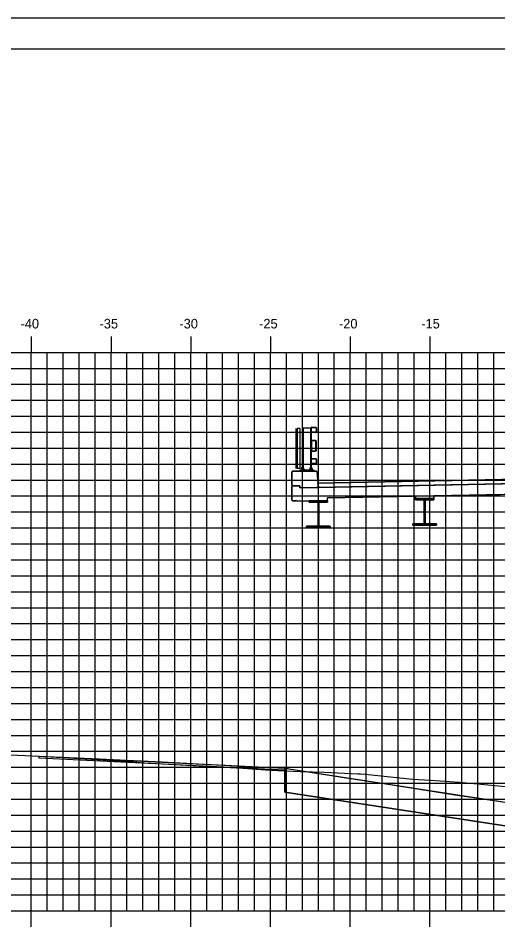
# Model space of a CAD drawing. Extents: x -22 to 1480, y -1511 to 8.
# Drawn here: x 463.6 to 493.7, y -131.7 to -74.5 of the extents above; entities that cross this region are included whole.
import ezdxf

# ---------------------------------------------------------------- set-up
doc = ezdxf.new("R2010")
doc.units = 0
for name, color, linetype in [('BORDER', 7, 'Continuous'), ('D_Bridge_Deck', 7, 'Continuous'), ('D_Bridge_Railing', 7, 'Continuous'), ('D_Bridge_Superstructure', 7, 'Continuous'), ('D_Bridge_Superstructure_Slab', 7, 'Continuous'), ('D_Roadway_Centerline', 7, 'Continuous'), ('D_Roadway_Edge_Shoulder', 7, 'Continuous'), ('D_Roadway_SlopeLines', 7, 'Continuous'), ('H_V ANNOTATION', 7, 'Continuous'), ('MAJOR', 7, 'Continuous'), ('MINOR', 7, 'Continuous'), ('PLOT BOUNDARY', 7, 'Continuous'), ('S_Roadway_Centerline', 7, 'Continuous')]:
    doc.layers.add(name, color=color, linetype=linetype)

msp = doc.modelspace()

# ---------------------------------------------------------------- linework, layer by layer
at = {"layer": 'BORDER'}
msp.add_line((589.452, -76.466), (429.452, -76.466), dxfattribs=at)
at = {"layer": 'D_Bridge_Deck'}
for p, q in [((481.286, -103.828), (480.827, -103.828)), ((481.286, -103.953), (481.286, -103.828))]:
    msp.add_line(p, q, dxfattribs=at)
for points in [[(480.827, -103.828), (480.786, -103.787), (480.786, -102.951), (480.827, -102.909), (482.327, -102.909), (482.372, -102.951), (482.452, -103.93)], [(481.077, -104.763), (481.786, -104.763)]]:
    msp.add_lwpolyline(points, dxfattribs=at)
at = {"layer": 'D_Bridge_Railing'}
for p, q in [((481.129, -100.242), (481.129, -102.734)), ((481.296, -100.242), (481.129, -100.242)), ((481.296, -100.242), (481.296, -102.734)), ((481.501, -100.201), (481.501, -102.733)), ((481.956, -100.201), (481.956, -102.733)), ((481.994, -100.451), (481.994, -100.201)), ((482.015, -100.451), (482.015, -100.201)), ((482.036, -100.159), (482.286, -100.159)), ((482.036, -100.18), (482.286, -100.18)), ((482.286, -100.472), (482.036, -100.472)), ((482.286, -100.492), (482.036, -100.492)), ((482.306, -100.201), (482.306, -100.451)), ((482.327, -100.201), (482.327, -100.451)), ((481.994, -101.044), (481.994, -101.607)), ((482.02, -101.044), (482.02, -101.607)), ((482.275, -100.992), (482.046, -100.992)), ((482.275, -101.018), (482.046, -101.018)), ((482.301, -101.607), (482.301, -101.044)), ((482.327, -101.607), (482.327, -101.044)), ((482.046, -101.633), (482.275, -101.633)), ((482.046, -101.659), (482.275, -101.659)), ((481.994, -102.409), (481.994, -102.159)), ((482.015, -102.409), (482.015, -102.159)), ((482.036, -102.117), (482.286, -102.117)), ((482.036, -102.138), (482.286, -102.138)), ((482.306, -102.159), (482.306, -102.409)), ((482.327, -102.159), (482.327, -102.409)), ((481.296, -102.734), (481.129, -102.734)), ((481.426, -102.659), (481.499, -102.659)), ((481.426, -102.667), (481.499, -102.667)), ((481.426, -102.675), (481.499, -102.675)), ((481.426, -102.684), (481.499, -102.684)), ((481.426, -102.692), (481.499, -102.692)), ((481.426, -102.7), (481.499, -102.7)), ((481.426, -102.709), (481.499, -102.709)), ((481.426, -102.717), (481.499, -102.717)), ((481.426, -102.725), (481.499, -102.725)), ((481.428, -102.74), (481.428, -102.796)), ((481.444, -102.663), (481.481, -102.663)), ((481.444, -102.671), (481.481, -102.671)), ((481.444, -102.68), (481.481, -102.68)), ((481.444, -102.688), (481.481, -102.688)), ((481.444, -102.696), (481.481, -102.696)), ((481.444, -102.704), (481.481, -102.704)), ((481.444, -102.713), (481.481, -102.713)), ((481.444, -102.721), (481.481, -102.721)), ((481.444, -102.729), (481.481, -102.729)), ((481.497, -102.74), (481.497, -102.796)), ((481.958, -102.659), (482.03, -102.659)), ((481.958, -102.667), (482.03, -102.667)), ((481.958, -102.675), (482.03, -102.675)), ((481.958, -102.684), (482.03, -102.684)), ((481.958, -102.692), (482.03, -102.692)), ((481.958, -102.7), (482.03, -102.7)), ((481.958, -102.709), (482.03, -102.709)), ((481.958, -102.717), (482.03, -102.717)), ((481.958, -102.725), (482.03, -102.725)), ((481.96, -102.74), (481.96, -102.796)), ((481.976, -102.663), (482.012, -102.663)), ((481.976, -102.671), (482.012, -102.671)), ((481.976, -102.68), (482.012, -102.68)), ((481.976, -102.688), (482.012, -102.688)), ((481.976, -102.696), (482.012, -102.696)), ((481.976, -102.704), (482.012, -102.704)), ((481.976, -102.713), (482.012, -102.713)), ((481.976, -102.721), (482.012, -102.721)), ((481.976, -102.729), (482.012, -102.729)), ((482.028, -102.74), (482.028, -102.796)), ((482.286, -102.43), (482.036, -102.43)), ((482.286, -102.451), (482.036, -102.451))]:
    msp.add_line(p, q, dxfattribs=at)
for points in [[(481.046, -100.242), (481.046, -102.734)], [(481.462, -102.651), (481.462, -100.201), (481.994, -100.201), (481.994, -102.651)], [(481.426, -102.733), (481.426, -102.659), (481.435, -102.651), (481.491, -102.651), (481.499, -102.659), (481.499, -102.733)], [(481.958, -102.733), (481.958, -102.659), (481.966, -102.651), (482.022, -102.651), (482.03, -102.659), (482.03, -102.733)]]:
    msp.add_lwpolyline(points, dxfattribs=at)
for points in [[(481.318, -102.817), (482.138, -102.817), (482.138, -102.899), (481.318, -102.899)], [(481.318, -102.899), (482.138, -102.899), (482.138, -102.909), (481.318, -102.909)], [(481.39, -102.817), (481.536, -102.817), (481.536, -102.804), (481.39, -102.804)], [(481.394, -102.74), (481.408, -102.733), (481.518, -102.733), (481.532, -102.74), (481.532, -102.796), (481.518, -102.804), (481.408, -102.804), (481.394, -102.796)], [(481.921, -102.817), (482.067, -102.817), (482.067, -102.804), (481.921, -102.804)], [(481.925, -102.74), (481.939, -102.733), (482.049, -102.733), (482.063, -102.74), (482.063, -102.796), (482.049, -102.804), (481.939, -102.804), (481.925, -102.796)]]:
    msp.add_lwpolyline(points, close=True, dxfattribs=at)
for centre, radius, start, end in [((482.036, -100.201), 0.0417, 90, 180), ((482.036, -100.451), 0.0417, 180, 270), ((482.036, -100.201), 0.0208, 90, 180), ((482.036, -100.451), 0.0208, 180, 270), ((482.286, -100.201), 0.0417, 0, 90), ((482.286, -100.201), 0.0208, 0, 90), ((482.286, -100.451), 0.0417, 270, 0), ((482.286, -100.451), 0.0208, 270, 0), ((482.046, -101.044), 0.052, 90, 180), ((482.046, -101.044), 0.026, 90, 180), ((482.275, -101.044), 0.052, 0, 90), ((482.275, -101.044), 0.026, 0, 90), ((482.046, -101.607), 0.052, 180, 270), ((482.046, -101.607), 0.026, 180, 270), ((482.275, -101.607), 0.052, 270, 0), ((482.275, -101.607), 0.026, 270, 0), ((482.036, -102.159), 0.0417, 90, 180), ((482.036, -102.159), 0.0208, 90, 180), ((482.286, -102.159), 0.0417, 0, 90), ((482.286, -102.159), 0.0208, 0, 90), ((481.411, -102.765), 0.0302, 55.4339, 120), ((481.411, -102.771), 0.0302, 240, 304.5661), ((481.463, -102.849), 0.114, 72.412, 107.588), ((481.463, -102.688), 0.114, 252.412, 287.588), ((481.514, -102.765), 0.0302, 60, 124.5661), ((481.514, -102.771), 0.0302, 235.4339, 300), ((481.942, -102.765), 0.0302, 55.4339, 120), ((481.942, -102.771), 0.0302, 240, 304.5661), ((481.994, -102.849), 0.114, 72.412, 107.588), ((481.994, -102.688), 0.114, 252.412, 287.588), ((482.036, -102.409), 0.0417, 180, 270), ((482.036, -102.409), 0.0208, 180, 270), ((482.046, -102.765), 0.0302, 60, 124.5661), ((482.046, -102.771), 0.0302, 235.4339, 300), ((482.286, -102.409), 0.0417, 270, 0), ((482.286, -102.409), 0.0208, 270, 0)]:
    msp.add_arc(centre, radius, start, end, dxfattribs=at)
at = {"layer": 'D_Bridge_Superstructure'}
for p, q in [((489.702, -104.63), (488.536, -104.63)), ((488.536, -104.63), (488.536, -104.713)), ((489.702, -104.713), (489.702, -104.63)), ((483.036, -104.763), (481.869, -104.763)), ((481.869, -104.763), (481.869, -104.847)), ((482.473, -104.847), (482.432, -104.847)), ((482.473, -104.847), (482.432, -104.847)), ((482.473, -104.847), (483.036, -104.847)), ((483.036, -104.847), (483.036, -104.763)), ((489.14, -104.713), (489.098, -104.713)), ((489.14, -104.713), (489.098, -104.713)), ((489.14, -104.713), (489.702, -104.713)), ((482.432, -106.347), (481.702, -106.347)), ((481.702, -106.347), (481.702, -106.43)), ((482.432, -106.347), (481.702, -106.347)), ((482.473, -106.347), (482.432, -106.347)), ((482.473, -106.347), (482.432, -106.347)), ((489.098, -106.213), (488.369, -106.213)), ((488.369, -106.213), (488.369, -106.297)), ((489.098, -106.213), (488.369, -106.213)), ((489.14, -106.213), (489.098, -106.213)), ((489.14, -106.213), (489.098, -106.213))]:
    msp.add_line(p, q, dxfattribs=at)
for points in [[(488.536, -104.63), (489.702, -104.63), (489.702, -104.713), (488.536, -104.713)], [(481.869, -104.763), (483.036, -104.763), (483.036, -104.847), (481.869, -104.847)], [(482.432, -104.847), (482.473, -104.847), (482.473, -106.347), (482.432, -106.347)], [(489.098, -104.713), (489.14, -104.713), (489.14, -106.213), (489.098, -106.213)], [(481.702, -106.347), (483.202, -106.347), (483.202, -106.43), (481.702, -106.43)], [(488.369, -106.213), (489.869, -106.213), (489.869, -106.297), (488.369, -106.297)]]:
    msp.add_lwpolyline(points, close=True, dxfattribs=at)
for points in [[(489.14, -104.713), (489.702, -104.713), (489.702, -104.63), (488.536, -104.63), (488.536, -104.713), (489.098, -104.713), (489.14, -104.713)], [(482.473, -104.847), (483.036, -104.847), (483.036, -104.763), (481.869, -104.763), (481.869, -104.847), (482.432, -104.847), (482.473, -104.847)], [(481.869, -104.847), (482.432, -104.847), (482.473, -104.847)], [(482.432, -104.847), (482.432, -106.347), (482.473, -106.347), (482.473, -104.847)], [(482.432, -104.847), (482.432, -106.347), (482.473, -106.347), (482.473, -104.847)], [(488.536, -104.713), (489.098, -104.713), (489.14, -104.713)], [(489.098, -104.713), (489.098, -106.213), (489.14, -106.213), (489.14, -104.713)], [(489.098, -104.713), (489.098, -106.213), (489.14, -106.213), (489.14, -104.713)], [(481.702, -106.347), (481.702, -106.43), (483.202, -106.43), (483.202, -106.347), (482.473, -106.347)], [(481.702, -106.43), (483.202, -106.43), (483.202, -106.347), (482.473, -106.347)], [(488.369, -106.213), (488.369, -106.297), (489.869, -106.297), (489.869, -106.213), (489.14, -106.213)], [(488.369, -106.297), (489.869, -106.297), (489.869, -106.213), (489.14, -106.213)]]:
    msp.add_lwpolyline(points, dxfattribs=at)
at = {"layer": 'D_Bridge_Superstructure_Slab'}
for p, q in [((504.452, -103.49), (482.452, -103.93)), ((482.452, -103.93), (504.452, -103.49)), ((489.702, -104.452), (489.786, -104.45)), ((489.786, -104.45), (489.786, -104.45)), ((480.827, -104.763), (481.036, -104.763)), ((481.036, -104.763), (481.036, -104.722)), ((481.036, -104.722), (481.077, -104.763))]:
    msp.add_line(p, q, dxfattribs=at)
msp.add_lwpolyline([(482.452, -103.93), (482.372, -102.951), (482.327, -102.909), (480.827, -102.909), (480.786, -102.951), (480.786, -103.787), (480.827, -103.828), (481.286, -103.828), (481.286, -103.953)], close=True, dxfattribs=at)
for points in [[(504.452, -103.49), (481.286, -103.953), (481.286, -103.828), (480.827, -103.828), (480.786, -103.87), (480.786, -104.722), (480.827, -104.763), (481.036, -104.763), (481.036, -104.722), (481.077, -104.763), (483.036, -104.763), (483.036, -104.585), (488.536, -104.475), (488.536, -104.63), (489.702, -104.63), (489.702, -104.452), (489.786, -104.45), (491.119, -104.423), (495.202, -104.342)], [(508.64, -103.574), (504.452, -103.49), (481.286, -103.953)], [(508.64, -103.574), (504.452, -103.49), (482.452, -103.93), (482.43, -103.66), (504.452, -103.219), (508.64, -103.303)], [(508.64, -103.303), (504.452, -103.219), (482.43, -103.66), (482.452, -103.93)], [(481.036, -104.763), (480.827, -104.763), (480.786, -104.722), (480.786, -103.87), (480.827, -103.828)], [(481.286, -103.828), (480.827, -103.828), (480.786, -103.87), (480.786, -104.722), (480.827, -104.763)], [(482.452, -103.93), (481.286, -103.953), (481.286, -103.828)], [(481.786, -104.763), (483.036, -104.763), (483.036, -104.585)], [(483.036, -104.763), (483.036, -104.585), (488.536, -104.475), (488.536, -104.63), (489.702, -104.63), (489.702, -104.452)], [(488.536, -104.475), (483.036, -104.585)], [(489.702, -104.452), (489.702, -104.63), (488.536, -104.63), (488.536, -104.475)], [(495.202, -104.342), (489.702, -104.452)], [(489.786, -104.45), (491.119, -104.423), (495.202, -104.342)], [(481.036, -104.763), (481.036, -104.722), (481.077, -104.763)], [(481.036, -104.763), (481.036, -104.722), (481.077, -104.763)], [(481.077, -104.763), (481.786, -104.763), (481.869, -104.763), (483.036, -104.763)]]:
    msp.add_lwpolyline(points, dxfattribs=at)
at = {"layer": 'D_Roadway_Centerline'}
for points in [[(482.43, -103.66), (484.452, -103.619), (485.173, -103.605), (487.585, -103.556), (492.452, -103.459), (498.212, -103.344), (504.452, -103.219), (510.212, -103.334), (516.452, -103.459), (519.572, -103.584), (522.452, -103.699), (523.952, -103.759), (525.452, -103.819)], [(464.735, -120.758), (464.762, -120.759), (464.937, -120.767), (468.724, -120.944), (470.022, -121.008), (472.661, -121.133), (475.308, -121.266), (476.598, -121.328), (480.36, -121.519), (480.534, -121.546), (480.594, -121.555), (484.471, -122.162), (485.881, -122.382), (488.408, -122.778), (491.167, -123.209), (492.356, -123.386), (495.95, -123.918), (496.306, -123.878), (496.453, -123.862), (500.05, -123.457), (501.74, -123.267), (503.787, -123.034), (507.026, -122.664), (508.64, -122.47)]]:
    msp.add_lwpolyline(points, dxfattribs=at)
at = {"layer": 'D_Roadway_Edge_Shoulder'}
msp.add_lwpolyline([(464.937, -120.767), (480.36, -121.519), (480.36, -121.644), (464.937, -120.892)], close=True, dxfattribs=at)
at = {"layer": 'D_Roadway_SlopeLines'}
for points in [[(480.36, -121.519), (495.95, -123.918)], [(480.36, -121.519), (480.36, -123.019), (495.95, -125.418), (508.64, -123.97)]]:
    msp.add_lwpolyline(points, dxfattribs=at)
msp.add_lwpolyline([(480.36, -121.519), (495.95, -123.918), (508.64, -122.47), (508.64, -123.97), (495.95, -125.418), (480.36, -123.019)], close=True, dxfattribs=at)
at = {"layer": 'MAJOR'}
for p, q in [((464.452, -94.464), (464.452, -95.466)), ((469.452, -94.464), (469.452, -95.466)), ((474.452, -94.464), (474.452, -95.466)), ((479.452, -94.464), (479.452, -95.466)), ((484.452, -94.464), (484.452, -95.466)), ((489.452, -94.464), (489.452, -95.466)), ((434.452, -95.466), (574.452, -95.466)), ((434.452, -95.466), (574.452, -95.466)), ((464.452, -130.466), (464.452, -95.466)), ((469.452, -130.466), (469.452, -95.466)), ((474.452, -130.466), (474.452, -95.466)), ((479.452, -130.466), (479.452, -95.466)), ((484.452, -130.466), (484.452, -95.466)), ((489.452, -130.466), (489.452, -95.466)), ((434.452, -100.466), (574.452, -100.466)), ((434.452, -105.466), (574.452, -105.466)), ((434.452, -110.466), (574.452, -110.466)), ((434.452, -115.466), (574.452, -115.466)), ((434.452, -120.466), (574.452, -120.466)), ((434.452, -125.466), (574.452, -125.466)), ((434.452, -130.466), (574.452, -130.466)), ((434.452, -130.466), (574.452, -130.466)), ((464.452, -131.468), (464.452, -130.466)), ((469.452, -131.468), (469.452, -130.466)), ((474.452, -131.468), (474.452, -130.466)), ((479.452, -131.468), (479.452, -130.466)), ((484.452, -131.468), (484.452, -130.466)), ((489.452, -131.468), (489.452, -130.466))]:
    msp.add_line(p, q, dxfattribs=at)
at = {"layer": 'MINOR'}
for p, q in [((465.452, -130.466), (465.452, -95.466)), ((466.452, -130.466), (466.452, -95.466)), ((467.452, -130.466), (467.452, -95.466)), ((468.452, -130.466), (468.452, -95.466)), ((470.452, -130.466), (470.452, -95.466)), ((471.452, -130.466), (471.452, -95.466)), ((472.452, -130.466), (472.452, -95.466)), ((473.452, -130.466), (473.452, -95.466)), ((475.452, -130.466), (475.452, -95.466)), ((476.452, -130.466), (476.452, -95.466)), ((477.452, -130.466), (477.452, -95.466)), ((478.452, -130.466), (478.452, -95.466)), ((480.452, -130.466), (480.452, -95.466)), ((481.452, -130.466), (481.452, -95.466)), ((482.452, -130.466), (482.452, -95.466)), ((483.452, -130.466), (483.452, -95.466)), ((485.452, -130.466), (485.452, -95.466)), ((486.452, -130.466), (486.452, -95.466)), ((487.452, -130.466), (487.452, -95.466)), ((488.452, -130.466), (488.452, -95.466)), ((490.452, -130.466), (490.452, -95.466)), ((491.452, -130.466), (491.452, -95.466)), ((492.452, -130.466), (492.452, -95.466)), ((493.452, -130.466), (493.452, -95.466)), ((434.452, -96.466), (574.452, -96.466)), ((434.452, -97.466), (574.452, -97.466)), ((434.452, -98.466), (574.452, -98.466)), ((434.452, -99.466), (574.452, -99.466)), ((434.452, -101.466), (574.452, -101.466)), ((434.452, -102.466), (574.452, -102.466)), ((434.452, -103.466), (574.452, -103.466)), ((434.452, -104.466), (574.452, -104.466)), ((434.452, -106.466), (574.452, -106.466)), ((434.452, -107.466), (574.452, -107.466)), ((434.452, -108.466), (574.452, -108.466)), ((434.452, -109.466), (574.452, -109.466)), ((434.452, -111.466), (574.452, -111.466)), ((434.452, -112.466), (574.452, -112.466)), ((434.452, -113.466), (574.452, -113.466)), ((434.452, -114.466), (574.452, -114.466)), ((434.452, -116.466), (574.452, -116.466)), ((434.452, -117.466), (574.452, -117.466)), ((434.452, -118.466), (574.452, -118.466)), ((434.452, -119.466), (574.452, -119.466)), ((434.452, -121.466), (574.452, -121.466)), ((434.452, -122.466), (574.452, -122.466)), ((434.452, -123.466), (574.452, -123.466)), ((434.452, -124.466), (574.452, -124.466)), ((434.452, -126.466), (574.452, -126.466)), ((434.452, -127.466), (574.452, -127.466)), ((434.452, -128.466), (574.452, -128.466)), ((434.452, -129.466), (574.452, -129.466))]:
    msp.add_line(p, q, dxfattribs=at)
at = {"layer": 'PLOT BOUNDARY'}
msp.add_lwpolyline([(421.359, -184.525), (591.359, -184.525), (591.359, -74.525), (421.359, -74.525)], close=True, dxfattribs=at)
at = {"layer": 'S_Roadway_Centerline'}
msp.add_lwpolyline([(462.729, -120.659), (464.937, -120.767), (470.404, -121.091), (471.531, -121.185), (474.177, -121.342), (474.215, -121.344), (477.722, -121.528), (479.424, -121.645), (481.364, -121.737), (482.808, -121.77), (484.92, -121.868), (485.094, -121.877), (485.393, -121.908), (488.346, -122.211), (489.476, -122.282), (491.297, -122.404), (494.415, -122.684)], dxfattribs=at)

# ---------------------------------------------------------------- texts
at = {"layer": 'H_V ANNOTATION'}
for s, p in [('-40', (463.778, -93.966)), ('-35', (468.732, -93.966)), ('-30', (473.74, -93.966)), ('-25', (478.738, -93.966)), ('-20', (483.746, -93.966)), ('-15', (488.909, -93.966))]:
    msp.add_text(s, height=0.6, dxfattribs=at).set_placement(p)

doc.saveas('drawing.dxf')
